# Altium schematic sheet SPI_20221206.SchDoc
size A4
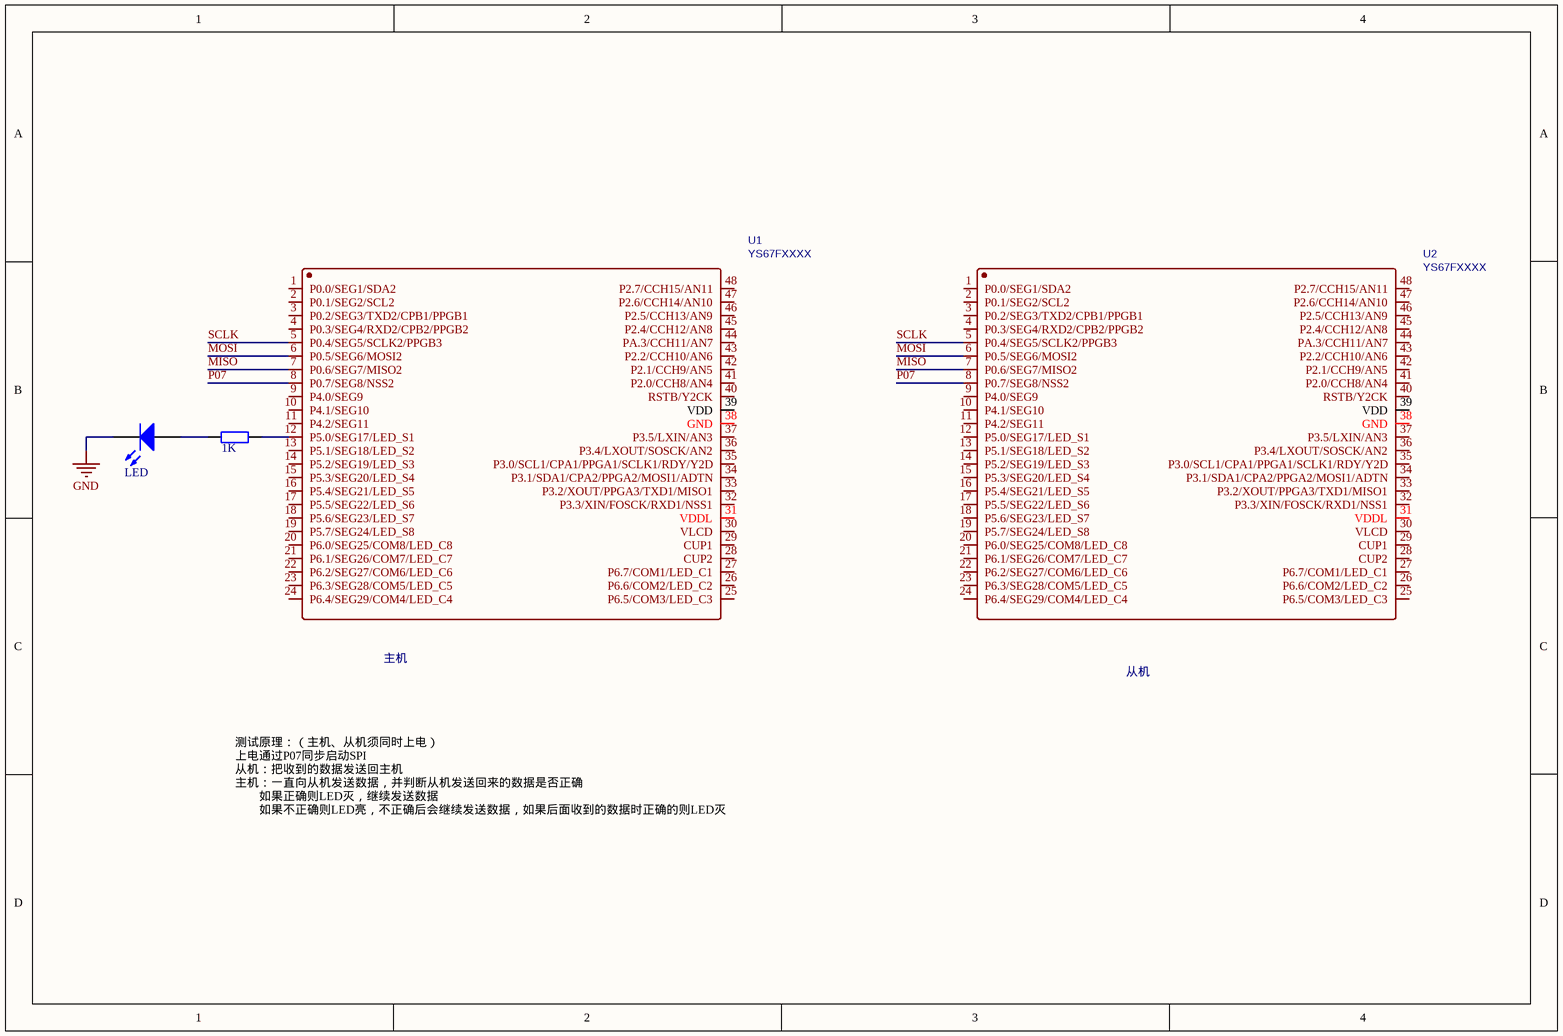
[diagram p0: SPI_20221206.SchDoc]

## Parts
DS?  LED  [LED-0]
R?  value 1K  [AXIAL-0.4]  (hidden comment: Res2)
U1  YS67FXXXX  [晶圆_DIE_6F30-1619X1736]
U2  YS67FXXXX  [晶圆_DIE_6F30-1619X1736]

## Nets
GND: DS?.2(K)
MISO: U1.7(P0.6/SEG7/MISO2) U2.7(P0.6/SEG7/MISO2)
MOSI: U1.6(P0.5/SEG6/MOSI2) U2.6(P0.5/SEG6/MOSI2)
P07: U1.8(P0.7/SEG8/NSS2) U2.8(P0.7/SEG8/NSS2)
SCLK: U1.5(P0.4/SEG5/SCLK2/PPGB3) U2.5(P0.4/SEG5/SCLK2/PPGB3)
NetDS?_1: DS?.1(A) R?.2
NetR?_1: R?.1 U1.12(P5.0/SEG17/LED_S1)

Not connected (* = marked no-connect by the designer): U1 1(P0.0/SEG1/SDA2) 2(P0.1/SEG2/SCL2) 3(P0.2/SEG3/TXD2/CPB1/PPGB1) 4(P0.3/SEG4/RXD2/CPB2/PPGB2) 9(P4.0/SEG9) 10(P4.1/SEG10) 11(P4.2/SEG11) 13(P5.1/SEG18/LED_S2) 14(P5.2/SEG19/LED_S3) 15(P5.3/SEG20/LED_S4) 16(P5.4/SEG21/LED_S5) 17(P5.5/SEG22/LED_S6) 18(P5.6/SEG23/LED_S7) 19(P5.7/SEG24/LED_S8) 20(P6.0/SEG25/COM8/LED_C8) 21(P6.1/SEG26/COM7/LED_C7) 22(P6.2/SEG27/COM6/LED_C6) 23(P6.3/SEG28/COM5/LED_C5) 24(P6.4/SEG29/COM4/LED_C4) 25(P6.5/COM3/LED_C3) 26(P6.6/COM2/LED_C2) 27(P6.7/COM1/LED_C1) 28(CUP2) 29(CUP1) 30(VLCD) 31(VDDL) 32(P3.3/XIN/FOSCK/RXD1/NSS1) 33(P3.2/XOUT/PPGA3/TXD1/MISO1) 34(P3.1/SDA1/CPA2/PPGA2/MOSI1/ADTN) 35(P3.0/SCL1/CPA1/PPGA1/SCLK1/RDY/Y2D) 36(P3.4/LXOUT/SOSCK/AN2) 37(P3.5/LXIN/AN3) 38(GND) 39(VDD) 40(RSTB/Y2CK) 41(P2.0/CCH8/AN4) 42(P2.1/CCH9/AN5) 43(P2.2/CCH10/AN6) 44(PA.3/CCH11/AN7) 45(P2.4/CCH12/AN8) 46(P2.5/CCH13/AN9) 47(P2.6/CCH14/AN10) 48(P2.7/CCH15/AN11); U2 1(P0.0/SEG1/SDA2) 2(P0.1/SEG2/SCL2) 3(P0.2/SEG3/TXD2/CPB1/PPGB1) 4(P0.3/SEG4/RXD2/CPB2/PPGB2) 9(P4.0/SEG9) 10(P4.1/SEG10) 11(P4.2/SEG11) 12(P5.0/SEG17/LED_S1) 13(P5.1/SEG18/LED_S2) 14(P5.2/SEG19/LED_S3) 15(P5.3/SEG20/LED_S4) 16(P5.4/SEG21/LED_S5) 17(P5.5/SEG22/LED_S6) 18(P5.6/SEG23/LED_S7) 19(P5.7/SEG24/LED_S8) 20(P6.0/SEG25/COM8/LED_C8) 21(P6.1/SEG26/COM7/LED_C7) 22(P6.2/SEG27/COM6/LED_C6) 23(P6.3/SEG28/COM5/LED_C5) 24(P6.4/SEG29/COM4/LED_C4) 25(P6.5/COM3/LED_C3) 26(P6.6/COM2/LED_C2) 27(P6.7/COM1/LED_C1) 28(CUP2) 29(CUP1) 30(VLCD) 31(VDDL) 32(P3.3/XIN/FOSCK/RXD1/NSS1) 33(P3.2/XOUT/PPGA3/TXD1/MISO1) 34(P3.1/SDA1/CPA2/PPGA2/MOSI1/ADTN) 35(P3.0/SCL1/CPA1/PPGA1/SCLK1/RDY/Y2D) 36(P3.4/LXOUT/SOSCK/AN2) 37(P3.5/LXIN/AN3) 38(GND) 39(VDD) 40(RSTB/Y2CK) 41(P2.0/CCH8/AN4) 42(P2.1/CCH9/AN5) 43(P2.2/CCH10/AN6) 44(PA.3/CCH11/AN7) 45(P2.4/CCH12/AN8) 46(P2.5/CCH13/AN9) 47(P2.6/CCH14/AN10) 48(P2.7/CCH15/AN11)

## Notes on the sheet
- 主机
- 从机
- 测试原理：（主机、从机须同时上电）
  上电通过P07同步启动SPI
  从机：把收到的数据发送回主机
  主机：一直向从机发送数据，并判断从机发送回来的数据是否正确
  如果正确则LED灭，继续发送数据
  如果不正确则LED亮，不正确后会继续发送数据，如果后面收到的数据时正确的则LED灭

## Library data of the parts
DS? = LED0: Typical INFRARED GaAs LED
R? = Res2: Resistor
U1 U2 = YS6F30LQFP48: BOM_Manufacturer: YS; Contributor: fossicker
